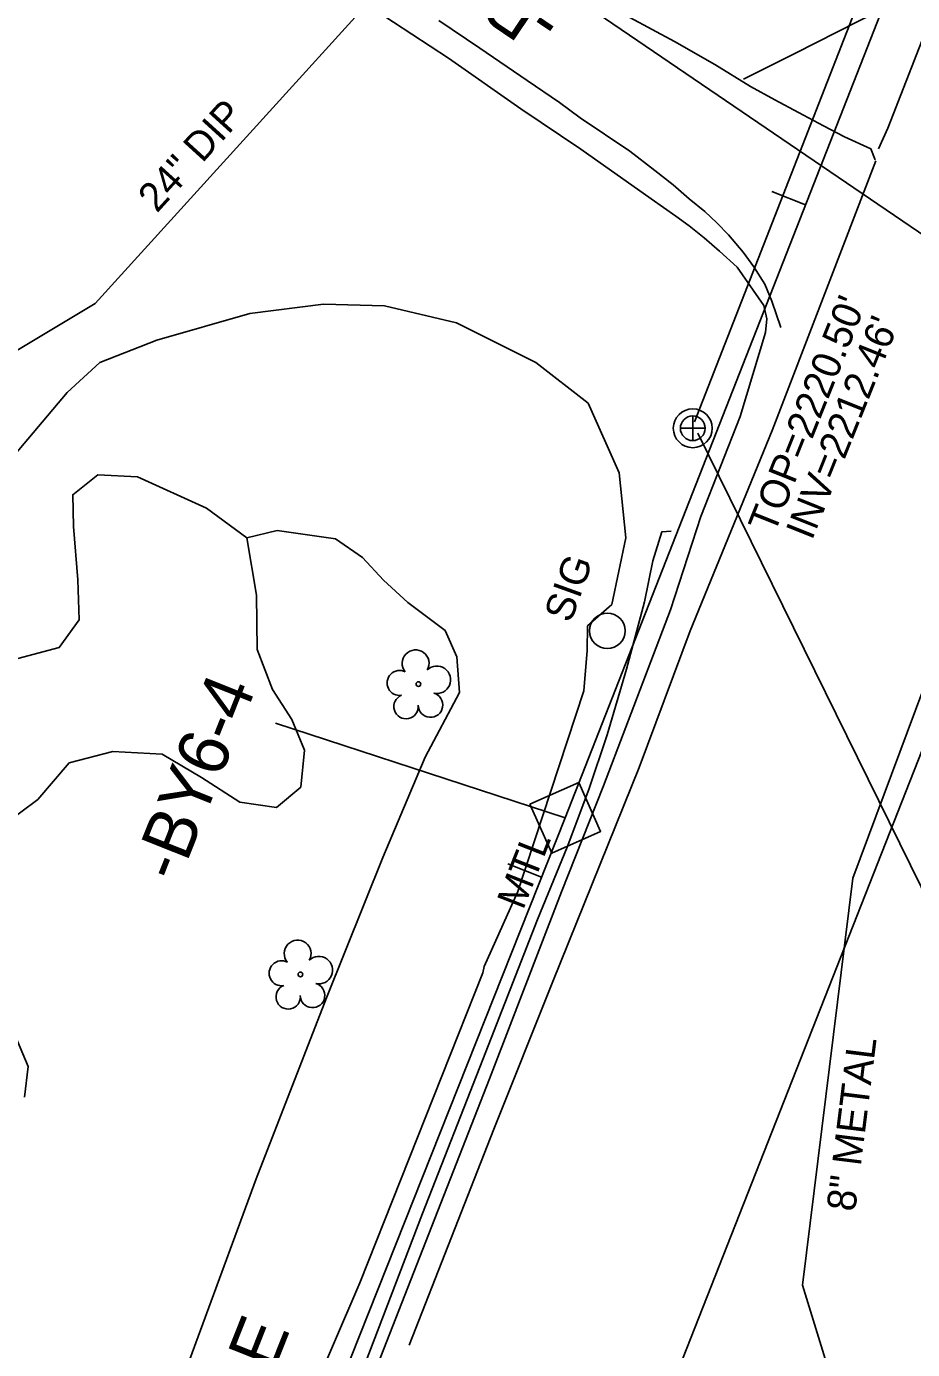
# Model space of a CAD drawing. Extents: x 945964 to 948456, y 631061 to 636061.
# Drawn here: x 947097.5 to 947220.2, y 634207.7 to 634390.9 of the extents above; entities that cross this region are included whole.
import ezdxf

# ---------------------------------------------------------------- set-up
doc = ezdxf.new("R2010")
doc.units = 0
for name, color, linetype in [('CTL Supplemental Horizontal and Vertical CELL', 7, 'Continuous'), ('Exist Guardrail', 7, 'Continuous'), ('Exist Guardrail Text', 7, 'Continuous'), ('Exist Horizontal Alignment', 7, 'Continuous'), ('Exist Horizontal Alignment Direction Label', 7, 'Continuous'), ('Exist Horizontal Baseline Alignment', 7, 'Continuous'), ('Exist Horizontal Baseline Alignment Direction Label', 7, 'Continuous'), ('Exist Horizontal Baseline Alignment Station Label', 7, 'Continuous'), ('Exist Horizontal Baseline Alignment Tick small', 7, 'Continuous'), ('Exist Roads EOP', 7, 'Continuous'), ('Exist Roads EOT', 7, 'Continuous'), ('Exist Utilities Gas UG Line SUE', 7, 'Continuous'), ('Exist Utilities Gas UG Line SUE Text', 7, 'Continuous'), ('Exist Utilities Other Pole CELL', 7, 'Continuous'), ('Exist Utilities Other Pole Text', 7, 'Continuous'), ('Exist Utilities Sanitary Sewer Manhole CELL', 7, 'Continuous'), ('Exist Utilities Sanitary Sewer Manhole Text', 7, 'Continuous'), ('Exist Utilities Sanitary Sewer UG Line', 7, 'Continuous'), ('Exist Utilities Sanitary Sewer UG Line Invert Elevation', 7, 'Continuous'), ('Exist Utilities Water UG Line SUE', 7, 'Continuous'), ('Exist Utilities Water UG Line SUE Text', 7, 'Continuous'), ('Exist Vegetation Hedge Row', 7, 'Continuous'), ('Exist Vegetation Tree CELL', 7, 'Continuous'), ('Exist Vegetation Woods Line', 7, 'Continuous')]:
    doc.layers.add(name, color=color, linetype=linetype)

# ---------------------------------------------------------------- blocks, each defined once
blk = doc.blocks.new('CTL SUPPLEMENTAL HORIZONTAL AND VERTICAL')
at = {"layer": 'CTL Supplemental Horizontal and Vertical CELL'}
blk.add_line((0, 0), (0, 0), dxfattribs=at)
blk.add_lwpolyline([(-0.0735, 0.074), (0.07475, 0.074), (0.07475, -0.0745), (-0.0735, -0.0745)], close=True, dxfattribs=at)

msp = doc.modelspace()

# ---------------------------------------------------------------- linework, layer by layer
at = {"layer": 'Exist Guardrail'}
msp.add_lwpolyline([(947128.25, 634163.66), (947136.59, 634185.55), (947144.9, 634207.15), (947152.31, 634226.55), (947160.68, 634247.87), (947168.26, 634267.24), (947172.35, 634277.26), (947175.36, 634285.27), (947177.87, 634292.84), (947180.57, 634301.93), (947183.06, 634311.21), (947184.2, 634316.9), (947185.45, 634320.91), (947186.73, 634321.01)], dxfattribs=at)
at = {"layer": 'Exist Horizontal Alignment'}
for p, q in [((946941.45, 633578.58), (947479.93, 634947.93)), ((947129.16, 634425), (947243.62, 634347.01))]:
    msp.add_line(p, q, dxfattribs=at)
at = {"layer": 'Exist Horizontal Baseline Alignment'}
for p, q in [((947172.06, 634281.32), (947352.87, 634742.36)), ((947008.79, 633870.13), (947172.06, 634281.32))]:
    msp.add_line(p, q, dxfattribs=at)
at = {"layer": 'Exist Horizontal Baseline Alignment Station Label'}
msp.add_line((947172.06, 634281.32), (947132, 634294.44), dxfattribs=at)
at = {"layer": 'Exist Horizontal Baseline Alignment Tick small'}
for p, q in [((947205.35, 634366.2), (947200.69, 634368.03)), ((947168.8, 634273.12), (947164.15, 634274.97))]:
    msp.add_line(p, q, dxfattribs=at)
at = {"layer": 'Exist Roads EOP'}
msp.add_lwpolyline([(947145.8, 634393.13), (947155.93, 634386.51), (947165.94, 634379.49), (947174.23, 634373.89), (947183.97, 634367.01), (947187.41, 634364.64), (947187.41, 634364.64), (947189.22, 634363.28), (947189.22, 634363.28), (947191.3, 634361.62), (947191.3, 634361.62), (947193.46, 634359.77), (947193.46, 634359.77), (947195.87, 634357.56), (947195.87, 634357.56), (947199.57, 634352.25), (947199.57, 634352.25), (947200.01, 634350.41), (947199.79, 634348.53), (947199.79, 634348.53), (947196.31, 634336.87), (947190.86, 634323.05), (947186.64, 634310.12), (947177.37, 634285.74), (947171.57, 634271.1), (947161.61, 634245.2), (947138.57, 634186.37)], dxfattribs=at)
at = {"layer": 'Exist Roads EOT'}
for points in [[(947203.79, 634418.45), (947209.88, 634421.27), (947215.14, 634424.03), (947220.64, 634427.5), (947225.22, 634430.94), (947230.5, 634435.02), (947235.52, 634439.4), (947240, 634444.07), (947245.07, 634449.25), (947239.13, 634434.02), (947235.18, 634424.04), (947228.77, 634407.68), (947221.8, 634389.81), (947216.76, 634376.81), (947215.46, 634373.93)], [(947196.76, 634383.6), (947203.96, 634387.18), (947218.4, 634394.55), (947213.44, 634404.22), (947205.69, 634419.28)], [(947201.93, 634349.22), (947200.69, 634352.85), (947199.7, 634355.22), (947198.2, 634357.59), (947196.72, 634359.64), (947194.68, 634362.03), (947193.05, 634363.68), (947191.43, 634365.25), (947189.26, 634367.03), (947187.02, 634368.97), (947184.5, 634370.93), (947181.01, 634373.63), (947174.14, 634378.25), (947171.28, 634380.36), (947166.8, 634383.38), (947160.25, 634387.88), (947154.61, 634391.71)], [(947181.05, 634392.14), (947187.22, 634388.81), (947192.78, 634385.62), (947197.73, 634382.59), (947201.1, 634380.7), (947204.38, 634378.96), (947207.85, 634377.12), (947210.74, 634375.61), (947214.39, 634373.95), (947215, 634372.43)], [(947150.5, 634208.33), (947162.19, 634238.23), (947170.35, 634258.68), (947182.31, 634288.3), (947189.37, 634307.21), (947200.73, 634334.94), (947215.07, 634372.28)]]:
    msp.add_lwpolyline(points, dxfattribs=at)
at = {"layer": 'Exist Utilities Gas UG Line SUE'}
msp.add_lwpolyline([(946938.69, 633388.44), (946952.02, 633429.96), (946984.05, 633495.07), (947022.62, 633581.51), (947031.8, 633599.49), (947055.84, 633629.91), (947132.75, 633749.08), (947144.07, 633762.63), (947222.37, 633850.77), (947272.45, 633907.66), (947293.81, 633936.23), (947292.1, 633948.39), (947269.88, 634027.14), (947218.39, 634172.85), (947204.91, 634216.63), (947211.91, 634272.96), (947250.67, 634376.88), (947282.1, 634456.81)], dxfattribs=at)
at = {"layer": 'Exist Utilities Other Pole CELL'}
msp.add_circle((947177.92, 634307.21), 2.46, dxfattribs=at)
at = {"layer": 'Exist Utilities Sanitary Sewer Manhole CELL'}
msp.add_lwpolyline([(947189.74, 634336.97), (947189.74, 634333.54), (947189.74, 634335.26), (947191.46, 634335.26), (947188.03, 634335.26)], dxfattribs=at)
for radius in [2.69, 1.71]:
    msp.add_circle((947189.74, 634335.26), radius, dxfattribs=at)
at = {"layer": 'Exist Utilities Sanitary Sewer UG Line'}
for p, q in [((947233.37, 634447.31), (947189.97, 634336.14)), ((947190.42, 634334.58), (947243.81, 634226.14))]:
    msp.add_line(p, q, dxfattribs=at)
at = {"layer": 'Exist Utilities Water UG Line SUE'}
msp.add_lwpolyline([(946885.48, 633607.31), (946857.92, 633638.18), (946810.43, 633705.26), (946774.88, 633780.55), (946773.35, 633783.79), (946747.51, 633849.62), (946734.48, 633879.25), (946712.81, 633944.6), (946701.3, 633998.92), (946703.12, 634056.04), (946710.69, 634080.44), (946738.48, 634116.01), (946775.16, 634148.01), (946829.92, 634190.2), (946881.2, 634227.62), (946932.03, 634251.13), (946980.62, 634279.25), (947003.27, 634299.27), (947064.64, 634327.09), (947107, 634352.54), (947145.27, 634394.7)], dxfattribs=at)
at = {"layer": 'Exist Vegetation Hedge Row'}
for points in [[(947059.88, 634291.69), (947070.61, 634306.57), (947075.72, 634311.5), (947084.46, 634319.23), (947093.67, 634329.04), (947103.13, 634340.21), (947107.68, 634344.36), (947115.57, 634347.46), (947128.45, 634351.13), (947138.61, 634352.44), (947147.07, 634352.21), (947157.02, 634349.84), (947168.04, 634344.36), (947175.26, 634338.74), (947179.54, 634329.08), (947180.47, 634320.08), (947178.54, 634310.87), (947175.16, 634307.9), (947175.12, 634304.5), (947174.65, 634298.89), (947165.52, 634271.12), (947160.85, 634260.77)], [(947146.83, 634275.84), (947152.71, 634289.75), (947157.45, 634298.67), (947157.08, 634303.6), (947155.45, 634307.28), (947150.32, 634311.13), (947146.92, 634314.23), (947144.01, 634317.35), (947140.31, 634319.96), (947132.22, 634321.11), (947128, 634320.07)], [(947113.89, 634189.45), (947129.3, 634231.37), (947139.02, 634256.4), (947146.83, 634275.83)], [(947160.85, 634260.77), (947160.67, 634259.89), (947143.64, 634216.98), (947128.12, 634180.73)]]:
    msp.add_lwpolyline(points, dxfattribs=at)
at = {"layer": 'Exist Vegetation Tree CELL'}
for p, q in [((947151.77, 634299.85), (947151.77, 634299.85)), ((947135.44, 634259.66), (947135.44, 634259.66))]:
    msp.add_line(p, q, dxfattribs=at)
for centre in [(947151.77, 634299.85), (947135.44, 634259.66)]:
    msp.add_circle(centre, 0.326, dxfattribs=at)
for centre, radius, start, end in [((947151.38, 634302.72), 1.86, 330.1651, 219.7134), ((947149.16, 634300), 1.73, 62.6636, 279.3457), ((947154.32, 634300.44), 1.9, 257.1011, 134.1999), ((947150.06, 634296.73), 1.69, 111.5671, 6.231), ((947153.44, 634296.95), 1.7, 181.2822, 74.56), ((947135.05, 634262.54), 1.86, 330.1651, 219.7134), ((947132.83, 634259.82), 1.73, 62.6636, 279.3457), ((947137.99, 634260.25), 1.9, 257.1011, 134.1999), ((947133.74, 634256.54), 1.69, 111.5671, 6.231), ((947137.11, 634256.76), 1.7, 181.2822, 74.56)]:
    msp.add_arc(centre, radius, start, end, dxfattribs=at)
at = {"layer": 'Exist Vegetation Woods Line'}
for points in [[(947096.34, 634303.38), (947102.06, 634304.89), (947104.82, 634308.73), (947104.62, 634314.27), (947104.03, 634321.66), (947103.93, 634326.06), (947107.41, 634328.83), (947112.89, 634328.53), (947122.44, 634324.21), (947128, 634320.07), (947129.34, 634312.15), (947129.45, 634304.61), (947131.57, 634299.08), (947134.26, 634294.96), (947136, 634290.69), (947135.47, 634285.59), (947132.11, 634282.74), (947127.03, 634283.51), (947121.76, 634286.93), (947116.3, 634290.13), (947109.49, 634290.53), (947103.43, 634288.94), (947099.1, 634283.89), (947094.4, 634280.35)], [(947094.18, 634255.33), (947097.77, 634246.91), (947097.23, 634242.64)]]:
    msp.add_lwpolyline(points, dxfattribs=at)

# ---------------------------------------------------------------- block references
at = {"layer": 'CTL Supplemental Horizontal and Vertical CELL', "xscale": 49.99999999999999, "yscale": 50, "rotation": 24.057662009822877}
msp.add_blockref('CTL SUPPLEMENTAL HORIZONTAL AND VERTICAL', (947172.06, 634281.32), dxfattribs=at)

# ---------------------------------------------------------------- texts
at = {"layer": 'Exist Guardrail Text'}
msp.add_text('MTL', height=4, rotation=68.5593, dxfattribs=at).set_placement((947166.26, 634268.46))
at = {"layer": 'Exist Horizontal Alignment Direction Label'}
msp.add_text('-RAMPD-', height=7, rotation=145.9492, dxfattribs=at).set_placement((947172.1, 634392.57))
at = {"layer": 'Exist Horizontal Baseline Alignment Direction Label'}
msp.add_text('N 21%%d 39\' 23.3" E', height=7, rotation=68.3435, dxfattribs=at).set_placement((947107.72, 634144.13))
at = {"layer": 'Exist Horizontal Baseline Alignment Station Label'}
msp.add_text('-BY6-4', height=7, rotation=68.3026, dxfattribs=at).set_placement((947118.53, 634272.14))
at = {"layer": 'Exist Utilities Gas UG Line SUE Text'}
msp.add_text('8" METAL', height=4, rotation=82.9183, dxfattribs=at).set_placement((947212.21, 634226.72))
at = {"layer": 'Exist Utilities Other Pole Text'}
msp.add_text('SIG', height=4, rotation=70.2144, dxfattribs=at).set_placement((947172.84, 634308.18))
at = {"layer": 'Exist Utilities Sanitary Sewer Manhole Text'}
msp.add_text("TOP=2220.50'", height=4, rotation=68.2551, dxfattribs=at).set_placement((947201.02, 634320.49))
at = {"layer": 'Exist Utilities Sanitary Sewer UG Line Invert Elevation'}
msp.add_text("INV=2212.46'", height=4, rotation=68.1117, dxfattribs=at).set_placement((947206.23, 634319.62))
at = {"layer": 'Exist Utilities Water UG Line SUE Text'}
msp.add_text('24" DIP', height=4, rotation=47.7631, dxfattribs=at).set_placement((947115.57, 634364.96))

doc.saveas('drawing.dxf')
